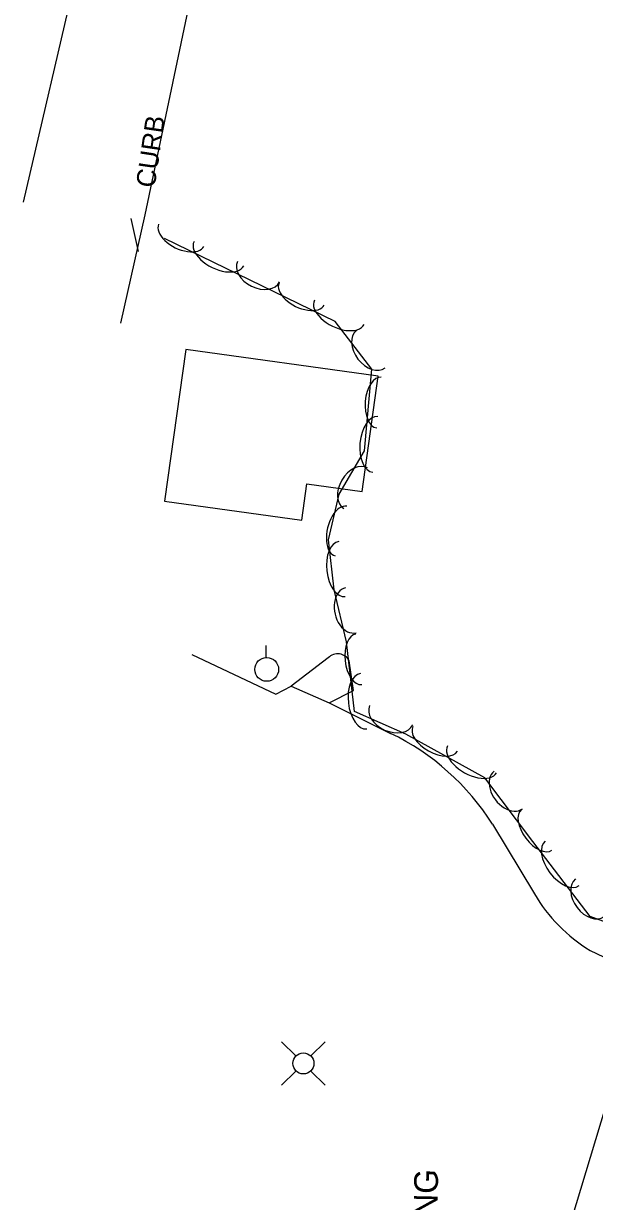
# Model space of a CAD drawing. Extents: x 978516 to 993312, y 1836504 to 1846212.
# Drawn here: x 992151.4 to 992271.4, y 1841641.6 to 1841889.2 of the extents above; entities that cross this region are included whole.
import ezdxf

# ---------------------------------------------------------------- set-up
doc = ezdxf.new("R2010")
doc.units = 0
for name, color, linetype in [('S_BUILDING', 7, 'Continuous'), ('S_CURB', 7, 'Continuous'), ('S_CURB_ANNOT', 7, 'Continuous'), ('S_EDGE_PAVEMENT', 7, 'Continuous'), ('S_PARKING', 7, 'Continuous'), ('S_PARKING_ANNOT', 7, 'Continuous'), ('S_TREE', 7, 'Continuous'), ('S_UTILITY_POLE', 7, 'Continuous')]:
    doc.layers.add(name, color=color, linetype=linetype)

msp = doc.modelspace()

# ---------------------------------------------------------------- linework, layer by layer
at = {"layer": 'S_BUILDING'}
msp.add_lwpolyline([(992185.48, 1841820.71), (992181.04, 1841788.83), (992209.88, 1841784.81), (992210.95, 1841792.48), (992222.59, 1841790.86), (992225.96, 1841815.08)], close=True, dxfattribs=at)
at = {"layer": 'S_CURB'}
msp.add_lwpolyline([(992175.51, 1841841.32), (992174.02, 1841848.27)], dxfattribs=at)
at = {"layer": 'S_EDGE_PAVEMENT'}
for points in [[(992238.76, 1842585.67), (992235.23, 1842514.78), (992231.64, 1842437.19), (992229.81, 1842400.05), (992225.51, 1842315.41), (992223.9, 1842274.97), (992221.91, 1842272.11), (992221.37, 1842257.73), (992222.1, 1842252.34), (992219.14, 1842214.27), (992217.36, 1842190.85), (992217.23, 1842168.1), (992216.9, 1842151.57), (992211.64, 1842074.66), (992207.08, 1842018.41), (992205.02, 1841998.18), (992202.17, 1841974.9), (992199.47, 1841957.2), (992193.58, 1841928.46), (992176.9, 1841849.01), (992171.73, 1841826.23)], [(992151.37, 1841851.68), (992162.67, 1841900.26), (992166.31, 1841919.52), (992170.24, 1841941.23), (992172.54, 1841957.14), (992174.23, 1841971.04), (992175.68, 1841984.89), (992180.02, 1842027.13), (992182.24, 1842046.15), (992185.95, 1842080.23), (992188.8, 1842110.33), (992193.15, 1842158.95), (992195.85, 1842194.71), (992196.94, 1842211.22), (992198.7, 1842231.92), (992202.36, 1842282.55), (992204.73, 1842329.07), (992206.44, 1842362.29)]]:
    msp.add_lwpolyline(points, dxfattribs=at)
at = {"layer": 'S_PARKING'}
for points in [[(992186.77, 1841756.62), (992204.39, 1841748.24), (992207.64, 1841749.95), (992215.65, 1841746.45), (992228.55, 1841740)], [(992215.43, 1841755.89), (992207.64, 1841749.95)], [(992215.65, 1841746.45), (992220.72, 1841749.01), (992219.84, 1841755.27)], [(992249.97, 1841720.89), (992258.77, 1841706.26)], [(992270.48, 1841694.38), (992281.96, 1841688.92), (992266.45, 1841637.41), (992253.5, 1841595.19), (992246.2, 1841570.07), (992233.19, 1841574.04)]]:
    msp.add_lwpolyline(points, dxfattribs=at)
msp.add_arc((992217.41, 1841754), 2.74, 27.5969, 136.2172, dxfattribs=at)
for centre, major_axis, ratio, start_param, end_param in [((992207.03, 1841693.95), (-31.38, 40.68), 0.986551, 4.616913, 5.1835), ((992288.62, 1841723.97), (20.93, -27.69), 0.999933, 4.600607, 5.08586)]:
    msp.add_ellipse(centre, major_axis=major_axis, ratio=ratio, start_param=start_param, end_param=end_param, dxfattribs=at)
at = {"layer": 'S_TREE'}
msp.add_lwpolyline([(992359.3, 1841629.27), (992365, 1841645.4), (992352.1, 1841662.7), (992337.5, 1841678.09), (992321.71, 1841684.64), (992301.66, 1841692.02), (992282.25, 1841697.17), (992270.47, 1841701.5), (992258.43, 1841717.31), (992248.35, 1841730.66), (992231.72, 1841739.85), (992220.97, 1841744.64), (992219.29, 1841759.25), (992216.69, 1841770.2), (992215.5, 1841780.66), (992217.74, 1841790.3), (992223.06, 1841799.4), (992224.59, 1841816.59), (992216.89, 1841826.57), (992181, 1841844.06)], dxfattribs=at)
for centre, major_axis, ratio, start_param, end_param in [((992184.54, 1841844.7), (4.76, -2.32), 0.546139, 3.142598, 6.284191), ((992192.43, 1841840.85), (5.22, -2.55), 0.555614, 3.142631, 6.284224), ((992200.78, 1841837.07), (4.41, -2.15), 0.692205, 3.14331, 6.284902), ((992209.84, 1841832.37), (4.76, -2.32), 0.546139, 3.142598, 6.284191), ((992217.73, 1841828.52), (5.22, -2.55), 0.555614, 3.142631, 6.284224), ((992224.37, 1841820.77), (3.03, -3.92), 0.684995, 3.141593, 6.283185), ((992226.09, 1841809.57), (-0.47, -5.33), 0.540028, 3.141593, 6.283185), ((992225.31, 1841800.74), (-0.52, -5.85), 0.549396, 3.141593, 6.283185), ((992221.21, 1841791.53), (-2.5, -4.28), 0.684487, 3.141593, 6.283185), ((992218.11, 1841782.53), (-1.21, -5.21), 0.54001, 3.141429, 6.283022), ((992218.33, 1841774.54), (0.65, -5.79), 0.553451, 3.146112, 6.287704), ((992220.16, 1841765.89), (1.08, -4.74), 0.697727, 3.15343, 6.295023), ((992221.85, 1841755.57), (0.61, -5.31), 0.540114, 3.141368, 6.28296), ((992222.86, 1841746.76), (0.67, -5.83), 0.549484, 3.141361, 6.282953), ((992228.67, 1841743.82), (4.53, -2.02), 0.685292, 3.141593, 6.283185), ((992237.91, 1841738.85), (4.68, -2.59), 0.54068, 3.14152, 6.283112), ((992245.67, 1841734.56), (5.14, -2.84), 0.55006, 3.141517, 6.28311), ((992253.27, 1841728.09), (2.97, -3.95), 0.686439, 3.144189, 6.285782), ((992259.26, 1841719.73), (3.21, -4.26), 0.54159, 3.143126, 6.284718), ((992264.62, 1841712.67), (3.55, -4.67), 0.549822, 3.141593, 6.283185), ((992270.44, 1841705.46), (3, -3.94), 0.68499, 3.141593, 6.283185)]:
    msp.add_ellipse(centre, major_axis=major_axis, ratio=ratio, start_param=start_param, end_param=end_param, dxfattribs=at)
at = {"layer": 'S_UTILITY_POLE'}
for p, q in [((992202.35, 1841755.97), (992202.35, 1841758.45)), ((992208.62, 1841672.21), (992205.63, 1841675.19)), ((992211.79, 1841672.21), (992214.78, 1841675.19)), ((992208.62, 1841669.03), (992205.63, 1841666.05)), ((992211.79, 1841669.03), (992214.78, 1841666.05))]:
    msp.add_line(p, q, dxfattribs=at)
for centre, radius in [((992202.49, 1841753.46), 2.5), ((992210.21, 1841670.63), 2.21)]:
    msp.add_circle(centre, radius, dxfattribs=at)

# ---------------------------------------------------------------- texts
at = {"layer": 'S_CURB_ANNOT'}
msp.add_text('CURB', height=4, rotation=81.7521, dxfattribs=at).set_placement((992178.93, 1841854.56))
at = {"layer": 'S_PARKING_ANNOT'}
msp.add_text('PAVED PARKING', height=5.0005, rotation=88.7241, dxfattribs=at).set_placement((992237.35, 1841593.76))

doc.saveas('drawing.dxf')
